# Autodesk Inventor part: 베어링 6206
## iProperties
Created: 2009-02
Part Number: 베어링 6206
Material: Steel, Mild
Description: 깊은 그루브 볼 베어링
Document SubType Name: Modeling
Standard: KS B 2023
Designer: KYOUNG IL JANG
Standards Organization: KS
Language: ko-KR
Size Designation: 6206 - 30 x 62 x 16
Categories: <MemberInstance><Categories><Category DisplayName="샤프트 부품" InternalName="7f7aeb1f-a693-4053-b835-cee3144e0d98" Mnemonic="SHFT"><Category DisplayName="베어링" Inter
Density: 1 g/cm^3
Company: 한국ATC센터
IsCustomPart: 0
Author: KYOUNG IL JANG
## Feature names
1. IDS_ARRAYBALL[SIMPL:T] [Circular Pattern]
